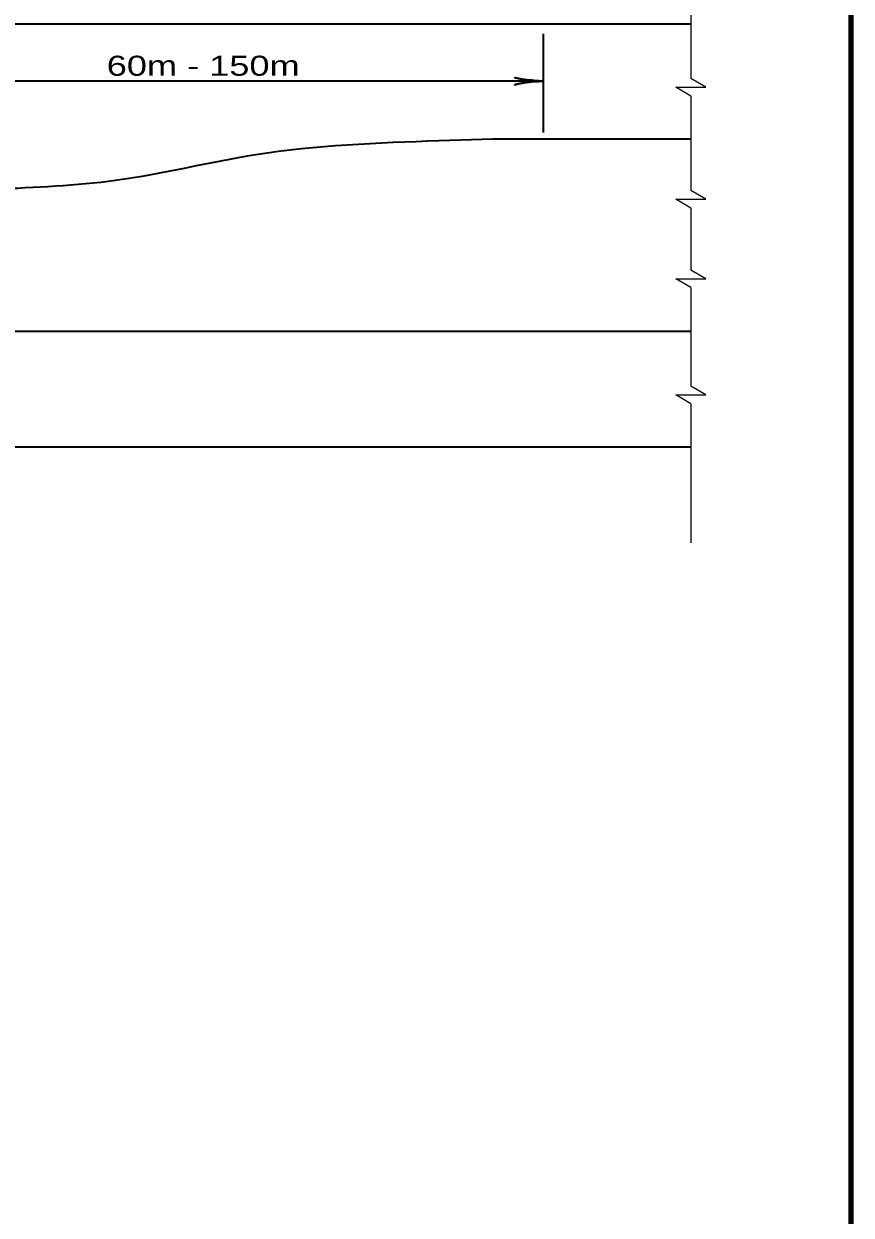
# Model space of a CAD drawing. Extents: x 1081 to 1936, y -630 to -24.
# Drawn here: x 1830.4 to 1929.6, y -330.4 to -187.6 of the extents above; entities that cross this region are included whole.
import ezdxf
from ezdxf.enums import TextEntityAlignment as Align

# ---------------------------------------------------------------- set-up
doc = ezdxf.new("R2010")
doc.units = 0
doc.layers.add('1', color=7, linetype='Continuous', lineweight=53)

msp = doc.modelspace()

# ---------------------------------------------------------------- linework, layer by layer
at = {"layer": '1', "lineweight": 158}
msp.add_line((1929.57, -556.37), (1929.57, -30.27), dxfattribs=at)
at = {"layer": '1', "lineweight": 13}
msp.add_line((1929.57, -556.37), (1929.57, -30.27), dxfattribs=at)
at = {"layer": '1', "lineweight": 25}
for p, q in [((1910.35, -177.514), (1910.35, -188.314)), ((1910.35, -188.314), (1910.35, -194.169)), ((1908.55, -195.226), (1912.15, -195.226)), ((1910.35, -196.284), (1908.55, -195.226)), ((1912.15, -195.226), (1910.35, -194.169)), ((1910.35, -196.284), (1910.35, -202.138)), ((1910.35, -202.138), (1910.35, -207.586)), ((1910.35, -209.702), (1908.55, -208.644)), ((1910.35, -209.702), (1910.35, -217.13)), ((1908.556, -218.19), (1912.156, -218.19)), ((1910.35, -219.245), (1908.556, -218.19)), ((1912.156, -218.19), (1910.35, -217.13)), ((1910.35, -219.245), (1910.35, -225.178)), ((1910.35, -225.178), (1910.35, -231.033)), ((1912.15, -232.09), (1910.35, -231.033)), ((1908.55, -232.09), (1912.15, -232.09)), ((1910.35, -233.148), (1908.55, -232.09)), ((1910.35, -233.148), (1910.35, -239.002)), ((1910.35, -239.002), (1910.35, -249.802))]:
    msp.add_line(p, q, dxfattribs=at)
at = {"layer": '1', "lineweight": 35}
for p, q in [((1772.44, -187.636), (1910.312, -187.636)), ((1892.659, -188.815), (1892.659, -200.637)), ((1892.659, -194.511), (1811.244, -194.511)), ((1886.632, -201.46), (1880.184, -201.652)), ((1910.312, -201.46), (1886.632, -201.46)), ((1910.312, -224.5), (1771.659, -224.5)), ((1772.44, -238.324), (1910.312, -238.324))]:
    msp.add_line(p, q, dxfattribs=at)
at = {"layer": '1', "lineweight": 25}
msp.add_lwpolyline([(1908.55, -208.644), (1912.15, -208.644), (1910.35, -207.586)], dxfattribs=at)
at = {"layer": '1', "lineweight": 40}
for centre, major_axis, ratio, start_param, end_param in [((1891.314, -194.257), (2.108, -0.211), 0.07063, 3.1407148, 5.41811), ((1891.314, -194.257), (2.108, -0.211), 0.07063, 3.1407148, 5.41811), ((1891.349, -194.843), (2.143, 0.187), 0.122415, 0.8963533, 3.1415927), ((1891.349, -194.843), (2.143, 0.187), 0.122415, 0.8963533, 3.1415927)]:
    msp.add_ellipse(centre, major_axis=major_axis, ratio=ratio, start_param=start_param, end_param=end_param, dxfattribs=at)
at = {"layer": '1', "lineweight": 35}
msp.add_spline([(1880.184, -201.652), (1858.232, -203.332), (1841.432, -206.404), (1826.968, -207.46)], degree=3, dxfattribs=at)

# ---------------------------------------------------------------- texts
at = {"layer": '1', "width": 1.35}
msp.add_text('60m - 150m', height=2.4, dxfattribs=at).set_placement((1851.921, -193.854), align=Align.CENTER)

doc.saveas('drawing.dxf')
